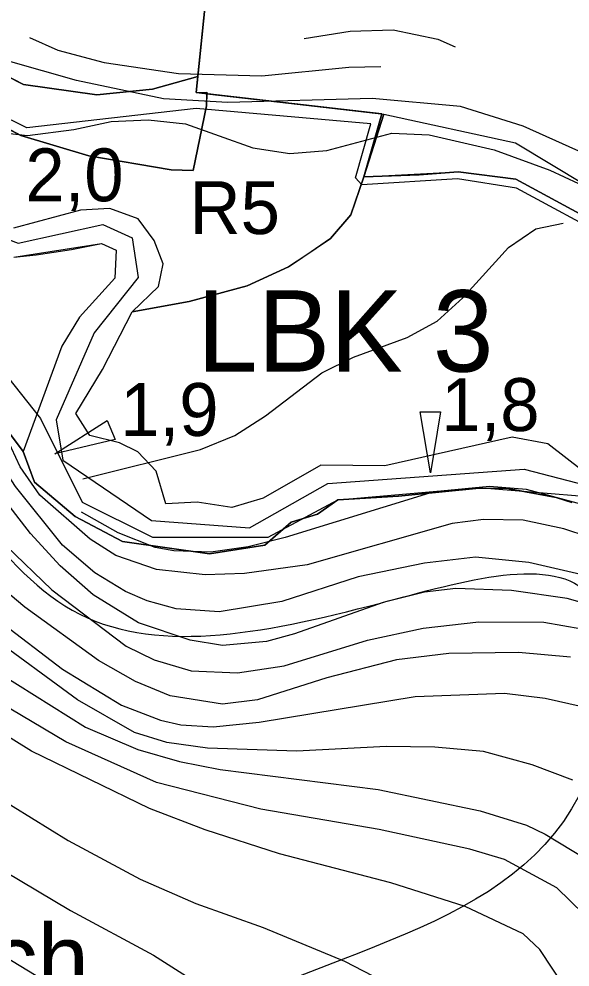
# Model space of a CAD drawing. Extents: x -684583 to -680383, y -1157874 to -1154904.
# Drawn here: x -683502.9 to -683367.4, y -1157116.7 to -1156883.6 of the extents above; entities that cross this region are included whole.
import ezdxf

# ---------------------------------------------------------------- set-up
doc = ezdxf.new("R2010")
doc.units = 0
for name, color, linetype in [('01_MÍSTNÍ_NÁZVY', 7, 'Continuous'), ('01_OBVOD PÚ', 7, 'Continuous'), ('01_PRVKY PRŮZKUMU', 7, 'Continuous'), ('01_VRSTEVNICE', 7, 'Continuous'), ('02_KULTURY STAV', 7, 'Continuous'), ('05_VHO_V_NÁDRŽ_STAV', 7, 'Continuous'), ('05_VHO_V_TOK', 7, 'Continuous'), ('06_BIOGEOGRAFIE', 7, 'Continuous'), ('06_ÚSES_BK', 7, 'Continuous')]:
    doc.layers.add(name, color=color, linetype=linetype)

msp = doc.modelspace()

# ---------------------------------------------------------------- linework, layer by layer
at = {"layer": '01_OBVOD PÚ'}
for points in [[(-683355.2, -1156936.88), (-683380.8, -1156922.96), (-683394.92, -1156921.16), (-683404.54, -1156921.9), (-683418.18, -1156922.4), (-683413.73, -1156906.92), (-683459.39, -1156901.7), (-683456.29, -1156871.3), (-683432.04, -1156877.37), (-683383.68, -1156876.28), (-683357.1, -1156874.68)], [(-683357.1, -1156874.68), (-683383.68, -1156876.28), (-683432.04, -1156877.37), (-683456.29, -1156871.3), (-683459.39, -1156901.7), (-683413.22, -1156907.01), (-683418.18, -1156922.4), (-683394.92, -1156921.16), (-683380.8, -1156922.96), (-683355.2, -1156936.88)]]:
    msp.add_lwpolyline(points, dxfattribs=at)
at = {"layer": '01_PRVKY PRŮZKUMU'}
msp.add_lwpolyline([(-683356.94, -1156938.03), (-683380.59, -1156925.22), (-683395.1, -1156922.91), (-683418.63, -1156924.37), (-683420.21, -1156922.66), (-683416.44, -1156909.37), (-683459.35, -1156905.59), (-683501.04, -1156910.34), (-683553.95, -1156884.24), (-683589.06, -1156852.53), (-683612.95, -1156822.77), (-683625.02, -1156800.2), (-683630.51, -1156838.26), (-683643.68, -1156883.02), (-683591.38, -1156911.2), (-683539.08, -1156946.2), (-683515.55, -1156959.38), (-683497.63, -1156981.82), (-683487.39, -1157002.43), (-683470.08, -1157010.97), (-683441.67, -1157010.97), (-683424.51, -1157001.8), (-683389.86, -1156998.77), (-683362.19, -1157001.09)], dxfattribs=at)
at = {"layer": '01_VRSTEVNICE'}
for points in [[(-683355.46, -1156920.38), (-683357.32, -1156920.38), (-683359.6, -1156918.67), (-683379, -1156909.97), (-683394.41, -1156905.12), (-683416.09, -1156903.12), (-683451.6, -1156904.12), (-683467.44, -1156903.26), (-683488.83, -1156898.7), (-683514.51, -1156891.42), (-683524.64, -1156887.14), (-683536.19, -1156880.15), (-683557.73, -1156864.75), (-683582.98, -1156844.92), (-683583.55, -1156843.64), (-683597.53, -1156831.09), (-683608.8, -1156823.38), (-683612.08, -1156820.24), (-683615.22, -1156814.68), (-683619.21, -1156804.55), (-683621.49, -1156791.72), (-683623.36, -1156785.52)], [(-683361.6, -1157020.95), (-683377.57, -1157017.24), (-683390.7, -1157015.95), (-683403.25, -1157017.38), (-683419.51, -1157020.8), (-683438.34, -1157026.79), (-683453.74, -1157029.36), (-683464.3, -1157028.65), (-683471.43, -1157026.65), (-683476.71, -1157024.37), (-683484.27, -1157019.8), (-683492.26, -1157012.96), (-683503.81, -1156998.55), (-683513.08, -1156984.28), (-683523.5, -1156971.16), (-683530.2, -1156964.89), (-683542.04, -1156955.33), (-683549.74, -1156947.77), (-683573.14, -1156918.67), (-683594.96, -1156898.13), (-683604.95, -1156893.14), (-683631.19, -1156886.29), (-683646.27, -1156880.82)], [(-683432.78, -1156888.43), (-683421.51, -1156886.57), (-683410.95, -1156886.29), (-683399.97, -1156888.57), (-683395.69, -1156890.43)], [(-683500.39, -1156888.14), (-683493.4, -1156891.28), (-683481.99, -1156894.28), (-683463.73, -1156896.99), (-683443.19, -1156897.56), (-683421.83, -1156895.43), (-683413.95, -1156895.28)], [(-683568.29, -1156890.71), (-683555.31, -1156894.42), (-683523.64, -1156907.54), (-683514.51, -1156910.68), (-683500.82, -1156912.25), (-683489.41, -1156910.82), (-683480.28, -1156908.83), (-683471.15, -1156908.4), (-683462.02, -1156909.4), (-683445.47, -1156915.25), (-683436.34, -1156916.67), (-683427.21, -1156915.96), (-683411.24, -1156911.68), (-683402.11, -1156912.11), (-683386.13, -1156915.82), (-683372.44, -1156920.81), (-683344.19, -1156933.93)], [(-683345.91, -1157032.36), (-683368.16, -1157026.08), (-683381.85, -1157024.08), (-683395.55, -1157023.65), (-683403.25, -1157024.51), (-683413.38, -1157027.08), (-683435.2, -1157034.78), (-683442.05, -1157036.64), (-683452.89, -1157037.63), (-683460.88, -1157036.35), (-683473.57, -1157032.07), (-683484.7, -1157025.22), (-683492.83, -1157018.09), (-683500.1, -1157010.1), (-683516.79, -1156988.56), (-683528.06, -1156976.58), (-683539.19, -1156966.74), (-683550.17, -1156958.47), (-683587.12, -1156933.36), (-683615.22, -1156909.82), (-683627.2, -1156901.12), (-683639.18, -1156894.85), (-683645.17, -1156893.14), (-683649.8, -1156892.67)], [(-683654.22, -1156899.1), (-683641.18, -1156902.98), (-683632.76, -1156907.4), (-683615.93, -1156918.95), (-683572.71, -1156954.76), (-683542.47, -1156977.58), (-683526.92, -1156991.42), (-683506.09, -1157013.1), (-683494.83, -1157023.94), (-683476.57, -1157037.78), (-683469.72, -1157041.2), (-683460.59, -1157043.91), (-683449.18, -1157044.34), (-683437.77, -1157042.63), (-683417.23, -1157036.35), (-683403.53, -1157033.35), (-683389.84, -1157031.79), (-683373.86, -1157031.93), (-683359.88, -1157034.35)], [(-683367.3, -1157040.49), (-683380.14, -1157039.35), (-683397.26, -1157039.63), (-683410.09, -1157041.2), (-683427.21, -1157045.62), (-683444.33, -1157051.04), (-683452.89, -1157052.04), (-683465.73, -1157050.04), (-683474.29, -1157046.48), (-683483.41, -1157041.34), (-683501.53, -1157028.22), (-683537.76, -1156997.84), (-683582.27, -1156957.47), (-683594.82, -1156946.91), (-683639.18, -1156913.53), (-683648.31, -1156908.54), (-683658.52, -1156905.34)], [(-683663.31, -1156912.31), (-683656.01, -1156913.25), (-683646.88, -1156916.67), (-683627.2, -1156928.94), (-683615.08, -1156937.64), (-683591.97, -1156956.04), (-683559.44, -1156987.28), (-683530.92, -1157011.1), (-683507.95, -1157031.5), (-683492.26, -1157043.48), (-683477.71, -1157052.33), (-683468.15, -1157056.03), (-683463.16, -1157057.18), (-683455.17, -1157057.6), (-683443.9, -1157056.46), (-683405.53, -1157050.19), (-683383.56, -1157049.33), (-683373.58, -1157050.61), (-683364.45, -1157052.61)], [(-683366.73, -1157070.73), (-683376.72, -1157067.02), (-683388.7, -1157063.74), (-683400.68, -1157062.6), (-683412.66, -1157062.45), (-683434.63, -1157063.6), (-683456.6, -1157062.88), (-683466.58, -1157061.46), (-683474.57, -1157059.03), (-683488.55, -1157051.04), (-683510.52, -1157034.92), (-683543.04, -1157008.96), (-683574.99, -1156981.86), (-683600.95, -1156957.04), (-683623.2, -1156938.21), (-683638.18, -1156928.51), (-683648.6, -1156923.23), (-683656.58, -1156920.52), (-683667.91, -1156919)], [(-683672.92, -1156926.15), (-683649.74, -1156930.94), (-683638.33, -1156935.93), (-683624.63, -1156945.49), (-683579.13, -1156987.14), (-683535.62, -1157022.66), (-683507.52, -1157044.62), (-683486.55, -1157057.75), (-683473.71, -1157063.17), (-683463.44, -1157066.16), (-683453.46, -1157068.16), (-683414.66, -1157073.01), (-683389.55, -1157078.29), (-683378.14, -1157081.85), (-683373.58, -1157083.99), (-683359.88, -1157092.27)], [(-683364.02, -1157103.68), (-683370.73, -1157097.26), (-683383.56, -1157090.27), (-683392.12, -1157087.7), (-683414.38, -1157082.85), (-683443.47, -1157077.86), (-683469.15, -1157071.3), (-683491.4, -1157061.31), (-683510.66, -1157049.9), (-683529.34, -1157035.35), (-683551.88, -1157015.24), (-683573.99, -1156996.7), (-683596.1, -1156980.29), (-683608.37, -1156969.59), (-683629.77, -1156948.62), (-683635.33, -1156944.2), (-683643.75, -1156939.07), (-683654.3, -1156935.07), (-683659.44, -1156933.93), (-683677.28, -1156932.2)], [(-683487.24, -1156996.7), (-683458.31, -1156989.42), (-683449.89, -1156986), (-683442.33, -1156981.15), (-683428.5, -1156970.59), (-683420.65, -1156966.74), (-683407.53, -1156961.89), (-683400.11, -1156957.9), (-683393.83, -1156952.19), (-683382.57, -1156939.78), (-683375.86, -1156935.22), (-683369.16, -1156933.79)], [(-683365.3, -1157131.78), (-683368.44, -1157122.08), (-683374.86, -1157112.38), (-683379, -1157108.53), (-683393.26, -1157101.82), (-683411.52, -1157095.98), (-683438.91, -1157088.84), (-683457.17, -1157082.99), (-683470.86, -1157077.72), (-683499.82, -1157063.59), (-683528.35, -1157045.91), (-683547.89, -1157030.79), (-683575.85, -1157006.82), (-683592.11, -1156995.84), (-683607.66, -1156983.86), (-683616.64, -1156975.3), (-683633.62, -1156955.9), (-683642.89, -1156946.91), (-683648.31, -1156943.78), (-683657.44, -1156940.49), (-683671.13, -1156938.35), (-683680.19, -1156936.23)], [(-683686.84, -1156945.45), (-683662.58, -1156953.33), (-683651.88, -1156958.32), (-683645.46, -1156962.6), (-683630.62, -1156976.58), (-683618.35, -1156987.14), (-683597.24, -1157003.11), (-683552.17, -1157042.91), (-683517.93, -1157068.87), (-683490.83, -1157085.56), (-683473.14, -1157095.12), (-683459.45, -1157101.11), (-683442.9, -1157106.96), (-683422.93, -1157115.23), (-683409.1, -1157122.36)], [(-683690.54, -1156950.59), (-683685.11, -1156953.62), (-683668.28, -1156960.61), (-683659.86, -1156965.17), (-683632.62, -1156984.86), (-683615.22, -1156999.26), (-683605.8, -1157008.25), (-683575.42, -1157039.77), (-683545.32, -1157066.31), (-683538.33, -1157071.73), (-683506.52, -1157093.12), (-683490.26, -1157102.82), (-683469.86, -1157113.81), (-683459.02, -1157120.65), (-683441.76, -1157133.78), (-683429.35, -1157145.76), (-683421.93, -1157156.03), (-683418.65, -1157163.73), (-683416.51, -1157174), (-683416.51, -1157186.84), (-683420.65, -1157199.25), (-683427.07, -1157209.8), (-683440.62, -1157225.5), (-683442.19, -1157226.49)], [(-683695.43, -1156957.37), (-683655.44, -1156981.72), (-683626.06, -1157002.12), (-683618.21, -1157008.68), (-683605.95, -1157020.95), (-683587.97, -1157042.06), (-683554.45, -1157079.14), (-683546.32, -1157086.56), (-683546.32, -1157087.13), (-683545.46, -1157087.27), (-683537.62, -1157094.12), (-683528.5, -1157099.52), (-683508.66, -1157112.81), (-683494.97, -1157121.08), (-683474.85, -1157135.2), (-683461.16, -1157148.61), (-683452.75, -1157160.88), (-683449.75, -1157166.87), (-683447.18, -1157174.86), (-683445.18, -1157190.12), (-683445.47, -1157196.25), (-683448.32, -1157209.95), (-683451.6, -1157218.08), (-683455.6, -1157224.35)], [(-683363.02, -1157010.96), (-683369.01, -1157008.96), (-683379, -1157006.82), (-683388.7, -1157006.68), (-683396.4, -1157007.68), (-683432.06, -1157017.81), (-683447.47, -1157019.95), (-683457.17, -1157020.23), (-683469.15, -1157018.95), (-683479.13, -1157015.52), (-683485.41, -1157011.53), (-683497.82, -1157000.69), (-683502.67, -1156993.7), (-683505.81, -1156986.85)], [(-683364.45, -1157002.97), (-683378.14, -1156999.26), (-683387.27, -1156998.55), (-683400.97, -1156999.83), (-683437.48, -1157011.1), (-683446.61, -1157013.38), (-683455.74, -1157014.67), (-683464.87, -1157014.38), (-683469.43, -1157013.53), (-683478.57, -1157009.96), (-683487.55, -1157004.83)]]:
    msp.add_lwpolyline(points, dxfattribs=at)
at = {"layer": '02_KULTURY STAV'}
for points in [[(-683432.04, -1156877.37), (-683456.29, -1156871.3), (-683458.99, -1156897.79), (-683470.08, -1156900.87), (-683483.78, -1156902.23), (-683501.85, -1156899.69), (-683541.87, -1156878.91), (-683570.35, -1156859.85), (-683584.63, -1156848.32), (-683595.13, -1156835.42), (-683606.54, -1156823.38), (-683615.78, -1156805.32), (-683625.32, -1156787.43), (-683612.82, -1156775.26), (-683604.88, -1156763.1), (-683590.79, -1156742.99), (-683585.06, -1156732.32), (-683579.12, -1156720.91), (-683571, -1156686.89), (-683565.38, -1156674.86), (-683524.73, -1156612.92)], [(-683357.1, -1156874.68), (-683383.68, -1156876.28), (-683432.04, -1156877.37), (-683456.29, -1156871.3), (-683459.39, -1156901.7), (-683413.22, -1156907.01), (-683380.86, -1156914.04), (-683355.11, -1156929.55)], [(-683541.87, -1156878.91), (-683515.11, -1156893), (-683501.85, -1156899.69), (-683483.78, -1156902.23), (-683470.08, -1156900.87), (-683458.99, -1156897.79), (-683459.39, -1156901.7), (-683456.72, -1156901.58), (-683456.8, -1156904.98), (-683460.14, -1156920.89), (-683465.54, -1156920.69), (-683485.77, -1156917.25), (-683502.44, -1156912.26), (-683538.6, -1156892.99), (-683555, -1156884.63), (-683571.77, -1156903.81), (-683575.1, -1156900.65), (-683575.07, -1156890.75), (-683578.07, -1156882.16)], [(-683513.15, -1156906.79), (-683502.44, -1156912.26), (-683485.77, -1156917.25), (-683465.54, -1156920.69), (-683460.14, -1156920.89), (-683456.8, -1156904.98), (-683456.73, -1156902), (-683413.73, -1156906.92), (-683418.18, -1156922.4), (-683421.34, -1156931.76), (-683426.31, -1156937.59), (-683432.41, -1156941.72), (-683436.68, -1156944.58), (-683446.81, -1156949.24), (-683461.08, -1156953.04), (-683475.13, -1156955.59), (-683468.62, -1156949.34), (-683467.51, -1156943.8), (-683469.69, -1156938.07), (-683473.65, -1156932.72), (-683480.61, -1156930.17), (-683487.85, -1156930.64), (-683504.32, -1156935.06)], [(-683364.12, -1156994.87), (-683372.87, -1156988.03), (-683381.69, -1156986.42), (-683413, -1156993.47), (-683428.71, -1156993.31), (-683442.93, -1157001.46), (-683450.6, -1157003.75), (-683459.12, -1157002.44), (-683466.8, -1157002.8), (-683469.19, -1156994.79), (-683473.75, -1156990.06), (-683478.19, -1156987.8), (-683485.5, -1156986), (-683488.97, -1156980.63), (-683482.4, -1156969.82), (-683475.13, -1156955.59), (-683461.08, -1156953.04), (-683446.81, -1156949.24), (-683436.68, -1156944.58), (-683426.31, -1156937.59), (-683421.34, -1156931.76), (-683418.18, -1156922.4), (-683404.54, -1156921.9), (-683394.92, -1156921.16), (-683380.8, -1156922.96), (-683355.2, -1156936.88)], [(-683364.12, -1156994.87), (-683372.87, -1156988.03), (-683381.69, -1156986.42), (-683413, -1156993.47), (-683428.71, -1156993.31), (-683442.93, -1157001.46), (-683450.6, -1157003.75), (-683459.12, -1157002.44), (-683466.8, -1157002.8), (-683469.19, -1156994.79), (-683473.75, -1156990.06), (-683478.19, -1156987.8), (-683485.5, -1156986), (-683488.97, -1156980.63), (-683482.4, -1156969.82), (-683475.13, -1156955.59), (-683468.62, -1156949.34), (-683467.51, -1156943.8), (-683469.69, -1156938.07), (-683473.65, -1156932.72), (-683480.61, -1156930.17), (-683487.85, -1156930.64), (-683504.32, -1156935.06)], [(-683504.17, -1156942.18), (-683482.62, -1156938.78), (-683479.08, -1156940.47), (-683479.34, -1156947.36), (-683488.04, -1156956.91), (-683492.44, -1156964.01), (-683501.91, -1156989.93), (-683514.24, -1156973.59)], [(-683504.17, -1156942.18), (-683498.67, -1156941.56), (-683490.02, -1156940.3), (-683482.62, -1156938.78), (-683479.08, -1156940.47), (-683479.34, -1156947.36), (-683488.04, -1156956.91), (-683492.44, -1156964.01), (-683501.91, -1156989.93), (-683499.08, -1156997.48), (-683489.16, -1157005.91), (-683477.5, -1157012.06), (-683456.08, -1157015.11), (-683442.47, -1157012.99), (-683436.02, -1157007.34), (-683429.51, -1157005.32), (-683424.51, -1157001.8), (-683409.61, -1157000.91), (-683389.75, -1156998.92), (-683382.84, -1156999.01), (-683370.86, -1157001.24), (-683367.03, -1157002.46)], [(-683514.24, -1156973.59), (-683501.91, -1156989.93), (-683499.08, -1156997.48), (-683489.16, -1157005.91), (-683477.5, -1157012.06), (-683456.08, -1157015.11), (-683442.47, -1157012.99), (-683436.02, -1157007.34), (-683429.51, -1157005.32), (-683424.51, -1157001.8), (-683409.61, -1157000.91), (-683389.75, -1156998.92), (-683382.84, -1156999.01), (-683370.86, -1157001.24), (-683367.03, -1157002.46)]]:
    msp.add_lwpolyline(points, dxfattribs=at)
msp.add_lwpolyline([(-683413.22, -1156907.01), (-683380.86, -1156914.04), (-683355.11, -1156929.55), (-683322.74, -1156944.05), (-683266.98, -1156959.79), (-683265.23, -1156955.91), (-683256.63, -1156961.33), (-683260.88, -1156962.95), (-683262.33, -1156963.5), (-683262.98, -1156960.35), (-683267.55, -1156961.29), (-683268.47, -1156965.64), (-683283.31, -1156963.36), (-683325.77, -1156948.29), (-683355.2, -1156936.88), (-683380.8, -1156922.96), (-683394.92, -1156921.16), (-683404.54, -1156921.9), (-683418.18, -1156922.4)], close=True, dxfattribs=at)
at = {"layer": '05_VHO_V_TOK'}
msp.add_lwpolyline([(-683640.3, -1156862.01), (-683631.63, -1156878.88), (-683623.57, -1156878.88), (-683616.93, -1156870.35), (-683615.42, -1156844.35), (-683604.61, -1156844.35), (-683593.47, -1156856.6), (-683579.25, -1156890.27), (-683576.17, -1156906.63), (-683556.43, -1156916.81), (-683533.66, -1156919.62), (-683513.12, -1156934.95), (-683503.17, -1156938.75), (-683482.31, -1156934.13), (-683475.08, -1156937.45), (-683473.66, -1156947.17), (-683484.44, -1156960.81), (-683493.81, -1156982.15), (-683492.15, -1156992.1), (-683470.34, -1157006.92), (-683446.29, -1157008.7), (-683426.97, -1156997.79), (-683378.73, -1156994.28), (-683361.67, -1156998.74)], dxfattribs=at)
for points in [[(-683404.27, -1156980.21), (-683399.27, -1156980.21), (-683401.77, -1156995.21)], [(-683481.27, -1156982.36), (-683479.3, -1156986.96), (-683494.08, -1156990.56)]]:
    msp.add_lwpolyline(points, close=True, dxfattribs=at)
at = {"layer": '06_BIOGEOGRAFIE'}
for points in [[(-683605.53, -1156693.94), (-683552.15, -1156773.17), (-683505.66, -1156862.74), (-683385.12, -1156876.52), (-683240.48, -1156867.91), (-682983.91, -1156935.09), (-682923.69, -1156998.38), (-682921.97, -1157094.84), (-682923.69, -1157198.19), (-682892.7, -1157272.26), (-682746.33, -1157329.1), (-682572.41, -1157337.72), (-682417.44, -1157289.49), (-682386.73, -1157266.62)], [(-683662.04, -1156787.77), (-683658.6, -1156877.34), (-683631.05, -1156927.29), (-683541.5, -1156975.52), (-683489.85, -1157028.92), (-683414.08, -1157027.2), (-683362.42, -1157025.48), (-683360.7, -1157063.37), (-683464.02, -1157132.27), (-683493.29, -1157163.28), (-683474.35, -1157189.11), (-683407.19, -1157171.89), (-683317.65, -1157115.05), (-683269.44, -1157104.71), (-683207.44, -1157173.61), (-683186.78, -1157259.74), (-683105.85, -1157416.48), (-683069.69, -1157530.17), (-683073.13, -1157580.12), (-683097.24, -1157628.35), (-683264.27, -1157657.63), (-683431.3, -1157647.3), (-683531.17, -1157605.96), (-683636.21, -1157542.23), (-683651.71, -1157521.56), (-683682.7, -1157519.83), (-683708.53, -1157528.45), (-683818.74, -1157547.39), (-683870.4, -1157518.11), (-683980.6, -1157521.56), (-684052.92, -1157490.55), (-684171.74, -1157400.98), (-684213.07, -1157375.14), (-684250.95, -1157388.92), (-684249.23, -1157437.15), (-684237.17, -1157466.44), (-684170.02, -1157518.11), (-684097.7, -1157562.9), (-684011.6, -1157605.96), (-683953.05, -1157602.51), (-683891.06, -1157626.63), (-683835.96, -1157619.74), (-683789.47, -1157599.07), (-683713.7, -1157578.4), (-683625.88, -1157592.18), (-683551.84, -1157667.97), (-683445.07, -1157736.87), (-683346.92, -1157771.32), (-683179.89, -1157767.87), (-683081.74, -1157773.04), (-683016.71, -1157810.65), (-682999.16, -1157844)]]:
    msp.add_spline(points, degree=3, dxfattribs=at)
at = {"layer": '06_ÚSES_BK'}
for points in [[(-683701.32, -1156718.39), (-683653.83, -1156730.68), (-683669.8, -1156745.42), (-683627.49, -1156781.02), (-683625.32, -1156787.43), (-683622.78, -1156794.5), (-683615.78, -1156805.32), (-683606.54, -1156823.38), (-683595.13, -1156835.42), (-683584.63, -1156848.32), (-683570.35, -1156859.85), (-683541.87, -1156878.91), (-683515.11, -1156893), (-683501.85, -1156899.69), (-683483.78, -1156902.23), (-683470.08, -1156900.87), (-683458.99, -1156897.79), (-683459.39, -1156901.7), (-683413.73, -1156906.92), (-683418.18, -1156922.4), (-683394.92, -1156921.16), (-683380.8, -1156922.96), (-683355.2, -1156936.88)], [(-683367.03, -1157002.46), (-683370.86, -1157001.24), (-683382.84, -1156999.01), (-683389.75, -1156998.92), (-683409.61, -1157000.91), (-683424.51, -1157001.8), (-683429.51, -1157005.32), (-683436.02, -1157007.34), (-683442.47, -1157012.99), (-683456.08, -1157015.11), (-683477.5, -1157012.06), (-683489.16, -1157005.91), (-683499.08, -1156997.48), (-683501.91, -1156989.93), (-683514.24, -1156973.59)]]:
    msp.add_lwpolyline(points, dxfattribs=at)

# ---------------------------------------------------------------- texts
at = {"layer": '01_MÍSTNÍ_NÁZVY'}
msp.add_text('Ve zmolách', height=17, dxfattribs=at).set_placement((-683604.52, -1157123.22))
at = {"layer": '05_VHO_V_NÁDRŽ_STAV'}
msp.add_text('R5', height=13, dxfattribs=at).set_placement((-683461, -1156936.49))
at = {"layer": '05_VHO_V_TOK'}
for s, p in [('2,0', (-683501.38, -1156928.43)), ('1,9', (-683478.03, -1156986.12)), ('1,8', (-683399.1, -1156984.92))]:
    msp.add_text(s, height=13, dxfattribs=at).set_placement(p)
at = {"layer": '06_ÚSES_BK'}
msp.add_text('LBK 3', height=20, dxfattribs=at).set_placement((-683459.14, -1156970.31))

doc.saveas('drawing.dxf')
